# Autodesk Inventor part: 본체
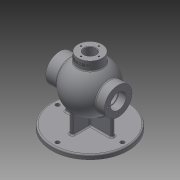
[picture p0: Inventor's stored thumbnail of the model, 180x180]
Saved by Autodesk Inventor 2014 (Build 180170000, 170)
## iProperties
Created: 2020-08
Part Number: 본체
Material: Generic
Document SubType Name: Modeling
Designer: kh
Density: 1 g/cm^3
Appearance: Default
Author: kh
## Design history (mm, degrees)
sketch "Sketch1"
  geometry: C1 r 85 at (0, 0); 1 further point
  constraints: 1 centre point, 1 coincident
  dimensions: "d0" = 170 diameter of C1
extrude "Extrusion1" new body sketch "Sketch1" distance "d1" = 10; taper "d2" = 0 deg
sketch "Sketch2"
  geometry: L1 (85, 10)-(-85, 10) reference; L2 (-85, 0)-(85, 0) reference; L3 (0, 0)-(0, 137.595); L4 (54.192, 85)-(43, 85); L5 (53, 85)-(43, 85); L6 (-43, 85)-(-53, 85); L7 (43, 85)-(-43, 85); A1 r 53 centre (0, 85) between (53, 85) and (-53, 85); A2 r 43 centre (0, 85) between (43, 85) and (-43, 85); 1 further point
  constraints: 10 end point, 4 collinear, 4 point on circle, 2 centre point, 2 coincident, 2 parallel, 2 point on line, 1 midpoint, 1 perpendicular
  dimensions: "d5" = 53 radius of A1; "d7" = 85 distance between parallel lines of L2 L7; "d8" = 43 radius of A2
revolve "Revolution1" sketch "Sketch2" stored, may be unused: angle "d9" = 90 deg
workplane "Work Plane1"
sketch "Sketch3"
  geometry: L1 (85, 10)-(-85, 10) reference; L2 (-85, 0)-(85, 0) reference; L3 (0, 0)-(0, 115.121); C1 r 31 at (0, 85)
  constraints: 2 end point, 1 centre point, 1 perpendicular, 1 point on line
  dimensions: "d11" = 62 diameter of C1; "d12" = 85 distance from line of L2 C1.centre
extrude "Extrusion2" join sketch "Sketch3" stored distance "d13" = 10; taper "d14" = 0 deg
workplane "Work Plane2"
sketch "Sketch4"
  geometry: L1 (0, 0)-(0, 109.575); L2 (-85, 0)-(85, 0) reference; C1 r 31 at (0, 85)
  constraints: 2 end point, 1 centre point, 1 point on line, 1 vertical
  dimensions: "d16" = 62 diameter of C1; "d17" = 85 distance from line of L2 C1.centre
extrude "Extrusion3" join sketch "Sketch4" stored distance "d18" = 10; taper "d19" = 0 deg
workplane "Work Plane3"
sketch "Sketch6"
  geometry: C1 r 27 at (0, 0); 1 further point
  constraints: 1 centre point, 1 coincident
  dimensions: "d24" = 54 diameter of C1
extrude "Extrusion5" join sketch "Sketch6" stored distance "d25" = 10; taper "d26" = 0 deg
sketch "Sketch12"
  geometry: L1 (-52, 4)-(52, 4); L2 (52, 4)-(52, -4); L3 (52, -4)-(-52, -4); L4 (-52, -4)-(-52, 4); L5 (0, 4)-(0, -4); 3 further points
  constraints: 10 end point, 4 midpoint, 2 parallel, 2 perpendicular, 1 coincident, 1 horizontal, 1 horizontal alignment, 1 other
  dimensions: "d36" = 104 distance of L1.start L1.end; "d37" = 8 distance of L1.end L2.end
extrude "Extrusion9" join sketch "Sketch12" stored distance "d38" = 1.75; taper "d39" = 0 deg
sketch "Sketch17"
  geometry: L1 (85, 10)-(-85, 10) reference; L2 (-43, 10)-(-43, 39.933); L3 (43, 10)-(43, 41.466); L4 (0, 0)-(0, 61.704)
  constraints: 6 end point, 2 parallel, 2 point on line, 1 perpendicular
  dimensions: "d44" = 43 distance from line of L2 L4.start; "d45" = 43 distance from line of L3 L4.start
feature "Rib1" dims "d46" = 1, "d47" = 8, "d48" = 0, "d49" = 0, "d50" = 1, "d51" = 1
feature "Rib2" dims "d52" = 1, "d53" = 8, "d54" = 0, "d55" = 0, "d56" = 1, "d57" = 1
sketch "Sketch18"
  geometry: C1 r 27 at (0, 0) reference; 1 further point
hole "Hole1" sketch "Sketch18" at (0, 0) diameter "d58" = 26; stored, may be unused: countersink angle "d62" = 90 deg, drill point angle "d64" = 0 deg; dims "d59" = 6, "d60" = 4, "d61" = 2, "d63" = 50
sketch "Sketch19" dims "d65" = 48
  geometry: L1 (0, 0)-(-24, 0); C1 r 31 at (0, 0) reference; 1 further point
  constraints: 2 end point, 1 coincident, 1 horizontal, 1 horizontal alignment, 2 other
hole "Hole2" sketch "Sketch19" at (-24, 0) diameter "d66" = 3.242; stored, may be unused: countersink angle "d70" = 90 deg, drill point angle "d72" = 118 deg; dims "d67" = 12, "d68" = 4, "d69" = 2, "d71" = 15
pattern_circular "Circular Pattern1" dims angle "d74" = 360 deg
sketch "Sketch20" dims "d76" = 48
  geometry: L1 (0, 0)-(24, 0); A1 r 31 centre (0, 0) between (-30.741, -4) and (-30.741, 4) reference; 1 further point
  constraints: 2 end point, 1 coincident, 1 horizontal, 1 horizontal alignment, 2 other
hole "Hole3" sketch "Sketch20" at (24, 0) diameter "d77" = 3.242; stored, may be unused: countersink angle "d81" = 90 deg, drill point angle "d83" = 118 deg; dims "d78" = 12, "d79" = 4, "d80" = 2, "d82" = 15
pattern_circular "Circular Pattern2" dims angle "d85" = 360 deg
sketch "Sketch21" dims "d87" = 40
  geometry: L1 (0, 0)-(0, 20); C1 r 27 at (0, 0) reference; 1 further point
  constraints: 2 end point, 1 coincident, 1 vertical, 1 vertical alignment, 2 other
hole "Hole4" sketch "Sketch21" at (0, 20) diameter "d88" = 3.242; stored, may be unused: countersink angle "d92" = 90 deg, drill point angle "d94" = 118 deg; dims "d89" = 12, "d90" = 4, "d91" = 2, "d93" = 15
pattern_circular "Circular Pattern3" dims angle "d96" = 360 deg
sketch "Sketch22"
  geometry: L1 (-72.5, 0)-(72.5, 0); L2 (0, -72.5)-(0, 72.5); C1 r 85 at (0, 0) reference; A1 r 72.5 centre (0, 0) between (-72.5, 0) and (72.5, 0); 2 further points
  constraints: 4 end point, 4 point on circle, 2 midpoint, 1 centre point, 1 coincident, 1 horizontal, 1 perpendicular
  dimensions: "d98" = 145 diameter of A1
hole "Hole5" sketch "Sketch22" at (-72.5, 0), (0, -72.5), (72.5, 0), (0, 72.5) diameter "d99" = 9; stored, may be unused: countersink angle "d103" = 90 deg, drill point angle "d105" = 0 deg; dims "d100" = 12, "d101" = 4, "d102" = 2, "d104" = 15
chamfer "Chamfer2" distance "d109" = 1; stored, may be unused: second distance "d110" = 2, angle "d111" = 45 deg
fillet "Fillet1" dims "d115" = 3
fillet "Fillet2" dims "d116" = 3
fillet "Fillet3" dims "d117" = 3
fillet "Fillet4" dims "d118" = 3
fillet "Fillet5" dims "d119" = 3
workplane "Work Plane4"
sketch "Sketch23"
  geometry: L1 (-27, 0)-(27, 0) reference; L2 (-27, -17.714)-(27, -17.714) reference; L3 (-27, 0)-(-27, -17.714) reference; L4 (27, 0)-(27, -17.714) reference; L5 (-20.739, -5.998)-(20.739, -5.998); L6 (20.739, -5.998)-(20.739, -12.002); L7 (20.739, -12.002)-(-20.739, -12.002); L8 (-20.739, -12.002)-(-20.739, -5.998); L9 (-20.739, -5.998)-(20.739, -12.002); 2 further points
  constraints: 2 end point, 1 midpoint, 2 other
  dimensions: "d120" = 27 distance from line of point (0, -9) L3; "d121" = 9 distance from line of point (0, -9) L1
emboss "Emboss1" sketch "Sketch23" dims "d0" = 170, "d122" = 0.5, "d123" = 0
sketch "Sketch25"
  geometry: C1 r 1.621 at (0, -24) reference; C2 r 1.621 at (24, 0) reference; C3 r 1.621 at (0, 24) reference; C4 r 1.621 at (-24, 0) reference; C5 r 31 at (0, 0) reference; C6 r 17.5 at (0, 0); 1 further point
  constraints: 1 centre point, 1 coincident
  dimensions: "d124" = 35 diameter of C6
extrude "Extrusion11" cut sketch "Sketch25" distance "d125" = 16; taper "d126" = 0 deg
sketch "Sketch26"
  geometry: C1 r 17.5 at (0, 0) reference; C2 r 18.5 at (0, 0); 1 further point
  constraints: 1 centre point, 1 coincident
  dimensions: "d127" = 37 diameter of C2
extrude "Extrusion12" cut sketch "Sketch26" distance "d128" = 1.75; taper "d129" = 0 deg
sketch "Sketch27"
  geometry: C1 r 18.5 at (0, 0) reference; C2 r 17.5 at (0, 0); 1 further point
  constraints: 1 centre point, 1 coincident
  dimensions: "d130" = 35 diameter of C2
extrude "Extrusion13" cut sketch "Sketch27" stored distance "d131" = 1.75; taper "d132" = 0 deg
body "Solid1"
node "Projected Loop1"
node "Projected Loop2"
node "Projected Loop9"
node "Projected Loop10"
node "Projected Loop11"
node "Projected Loop12"
node "Projected Loop13"
node "Projected Loop14"
node "Projected Loop15"
other parameters: "d3" = 85, "d10" = -68, "d15" = 63
